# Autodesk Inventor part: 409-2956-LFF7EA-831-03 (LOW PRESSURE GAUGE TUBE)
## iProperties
Created: 2010-09
Part Number: 409-2956-LFF7EA-831-03 (LOW PRESSURE GAUGE TUBE)
Material: 3/8" OD TUBE - SS
Document SubType Name: Modeling
Designer: S. Boerckel
Engineer: Steve Boerckel
Mass: 61.6007 g
Surface Area: 127.01 cm^2
Volume: 7.62385 cm^3
Density: 8.08 g/cm^3
Description: LOWE PRESSURE GAUGE TUBE
Length: 14.237 in
Author: S. Boerckel
Revision Number: 0
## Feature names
1. Sweep3
